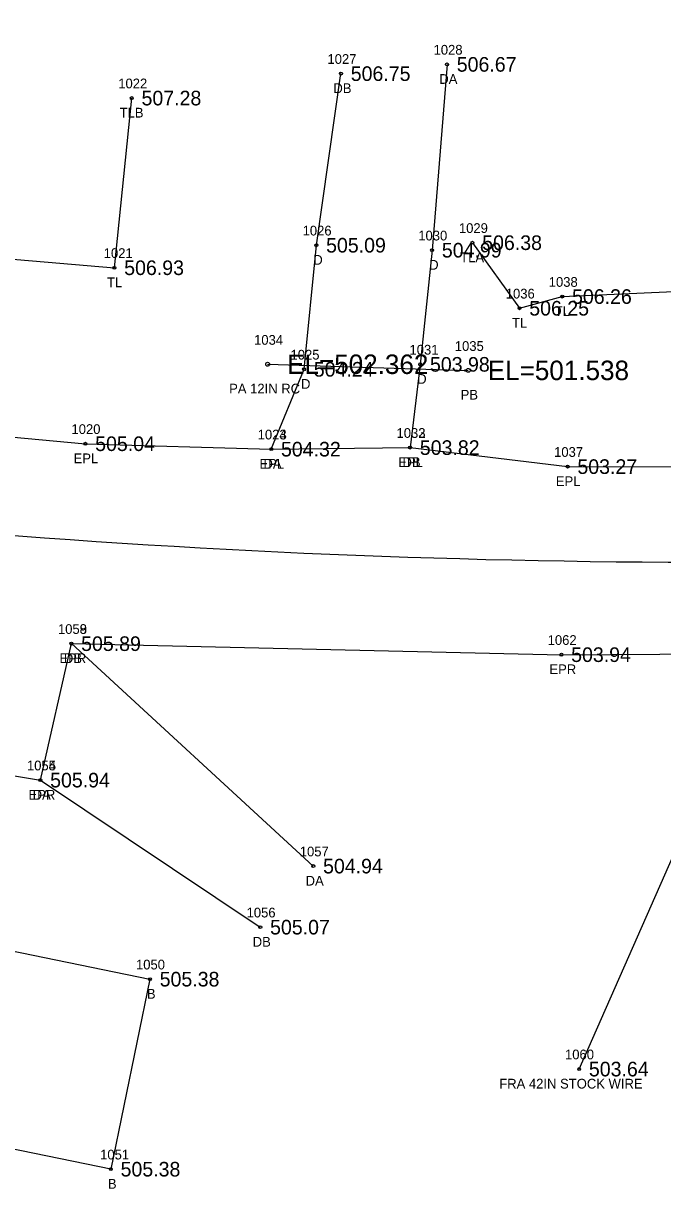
# Model space of a CAD drawing. Extents: x 1784103 to 1787401, y 770251 to 771298.
# Drawn here: x 1785175.5 to 1785241.1, y 770772 to 770891.7 of the extents above; entities that cross this region are included whole.
import ezdxf

# ---------------------------------------------------------------- set-up
doc = ezdxf.new("R2010")
doc.units = 0
for name, color, linetype in [('RD_EX_Bldg', 7, 'Continuous'), ('RD_EX_Bldg_txCode', 7, 'Continuous'), ('RD_EX_DR_Pipe', 7, 'Continuous'), ('RD_EX_DR_Pipe_txCode', 7, 'Continuous'), ('RD_EX_Driveway', 7, 'Continuous'), ('RD_EX_Driveway_txCode', 7, 'Continuous'), ('RD_EX_Fence_Other', 7, 'Continuous'), ('RD_EX_Fence_Other_txCode', 7, 'Continuous'), ('RD_EX_Road', 7, 'Continuous'), ('RD_EX_Road_txCode', 7, 'Continuous'), ('RD_EX_TX_Bldg_ELEV', 7, 'Continuous'), ('RD_EX_TX_Driveway_ELEV', 7, 'Continuous'), ('RD_EX_TX_Fence_Other_ELEV', 7, 'Continuous'), ('RD_EX_TX_Road_ELEV', 7, 'Continuous'), ('RD_EX_TX_VEG_ELEV', 7, 'Continuous'), ('RD_EX_VEG', 7, 'Continuous'), ('RD_EX_VEG_txCode', 7, 'Continuous'), ('RD_HC_Cl', 7, 'Continuous'), ('RD_SMD_Locator', 7, 'Continuous'), ('RD_TX_Pipe_ElevEX', 7, 'Continuous')]:
    doc.layers.add(name, color=color, linetype=linetype)

msp = doc.modelspace()

# ---------------------------------------------------------------- linework, layer by layer
at = {"layer": 'RD_EX_Bldg'}
msp.add_lwpolyline([(1785151.62, 770780.79), (1785156.03, 770800.21), (1785188.51, 770793.55), (1785184.5, 770774.04), (1785151.62, 770780.79)], dxfattribs=at)
at = {"layer": 'RD_EX_DR_Pipe'}
msp.add_line((1785200.59, 770856.69), (1785221.18, 770856.06), dxfattribs=at)
at = {"layer": 'RD_EX_Driveway'}
for p, q in [((1785205.28, 770805.16), (1785180.45, 770828)), ((1785177.27, 770813.99), (1785199.84, 770798.89))]:
    msp.add_line(p, q, dxfattribs=at)
for points in [[(1785219, 770887.48), (1785217.47, 770868.4), (1785216.25, 770856.68), (1785215.21, 770848.13)], [(1785200.96, 770847.97), (1785204.33, 770856.17), (1785205.59, 770868.91), (1785208.12, 770886.53)]]:
    msp.add_lwpolyline(points, dxfattribs=at)
at = {"layer": 'RD_EX_Fence_Other'}
msp.add_lwpolyline([(1785232.56, 770784.32), (1785243.65, 770809.45), (1785281.87, 770810.97), (1785330.77, 770810.35), (1785381.35, 770812.32), (1785481.48, 770815.35), (1785580.21, 770817.42), (1785680.43, 770820.14), (1785794.9, 770821.68), (1785847.9, 770822.69), (1785879.84, 770822.3), (1785979.43, 770826.69), (1786080.46, 770830.52), (1786182.98, 770833.3), (1786235.76, 770836.16), (1786247.48, 770836.31), (1786280.27, 770837.57), (1786379.57, 770841.87), (1786481.1, 770846.08), (1786539.49, 770848.17), (1786546.34, 770841.89)], dxfattribs=at)
at = {"layer": 'RD_EX_Road'}
for points in [[(1785083.87, 770860.72), (1785132.91, 770853.08), (1785181.89, 770848.53), (1785200.96, 770847.97), (1785215.21, 770848.13), (1785231.38, 770846.18), (1785281.19, 770846.16), (1785330.68, 770847.27), (1785380.41, 770849.82), (1785480.96, 770852.71), (1785580.09, 770856.45), (1785680.2, 770859.84), (1785779.71, 770863.4)], [(1785079.74, 770841.1), (1785077.36, 770829.81), (1785127.59, 770822.23), (1785177.27, 770813.99), (1785180.45, 770828), (1785230.74, 770826.87), (1785281.16, 770827.18), (1785331.14, 770828.42), (1785381.03, 770830.27), (1785481.34, 770833.99), (1785580.1, 770837.94), (1785680.6, 770840.57), (1785780.28, 770843.87)]]:
    msp.add_lwpolyline(points, dxfattribs=at)
at = {"layer": 'RD_EX_VEG'}
for points in [[(1785221.61, 770869.17), (1785226.44, 770862.44), (1785230.83, 770863.64), (1785281.61, 770865.88), (1785330.18, 770866.95), (1785378.64, 770865.28), (1785481.03, 770871.22), (1785579.9, 770882.43), (1785678.49, 770873.66), (1785753.25, 770880.69), (1785777.57, 770887.66), (1785796.72, 770894.6), (1785878.49, 770883.8), (1786077.63, 770894.05), (1786177.75, 770898.7), (1786232.19, 770912.93), (1786276.99, 770915.77), (1786313.89, 770919.94), (1786357.9, 770947.77)], [(1785087.02, 770879.15), (1785135.13, 770870.83), (1785184.87, 770866.6), (1785186.65, 770884.02)]]:
    msp.add_lwpolyline(points, dxfattribs=at)
at = {"layer": 'RD_HC_Cl'}
msp.add_arc((1785246.88, 771791.29), 954.93, 251.4323, 271.9359, dxfattribs=at)
at = {"layer": 'RD_SMD_Locator'}
for centre, radius in [((1785208.12, 770886.53), 0.15), ((1785219, 770887.48), 0.15), ((1785186.65, 770884.02), 0.15), ((1785205.59, 770868.91), 0.15), ((1785221.61, 770869.17), 0.15), ((1785217.47, 770868.4), 0.15), ((1785184.87, 770866.6), 0.15), ((1785230.83, 770863.64), 0.15), ((1785226.44, 770862.44), 0.15), ((1785200.59, 770856.69), 0.2), ((1785216.25, 770856.68), 0.15), ((1785204.33, 770856.17), 0.15), ((1785221.18, 770856.06), 0.2), ((1785181.89, 770848.53), 0.15), ((1785200.96, 770847.97), 0.15), ((1785200.96, 770847.97), 0.15), ((1785215.21, 770848.13), 0.15), ((1785215.21, 770848.13), 0.15), ((1785231.38, 770846.18), 0.15), ((1785180.45, 770828), 0.15), ((1785180.45, 770828), 0.15), ((1785230.74, 770826.87), 0.15), ((1785177.27, 770813.99), 0.15), ((1785177.27, 770813.99), 0.15), ((1785205.28, 770805.16), 0.15), ((1785199.84, 770798.89), 0.15), ((1785188.51, 770793.55), 0.15), ((1785232.56, 770784.32), 0.15), ((1785184.5, 770774.04), 0.15)]:
    msp.add_circle(centre, radius, dxfattribs=at)

# ---------------------------------------------------------------- texts
at = {"layer": 'RD_EX_Bldg_txCode'}
for s, p in [('1050', (1785187.08, 770794.55)), ('B', (1785188.2, 770791.55)), ('1051', (1785183.4, 770775.04)), ('B', (1785184.2, 770772.04))]:
    msp.add_text(s, height=1, dxfattribs=at).set_placement(p)
at = {"layer": 'RD_EX_DR_Pipe_txCode'}
for s, p in [('1034', (1785199.2, 770858.69)), ('1035', (1785219.8, 770858.06)), ('PA 12IN RC', (1785196.64, 770853.69)), ('PB', (1785220.4, 770853.06))]:
    msp.add_text(s, height=1, dxfattribs=at).set_placement(p)
at = {"layer": 'RD_EX_Driveway_txCode'}
for s, p in [('1028', (1785217.62, 770888.48)), ('1027', (1785206.73, 770887.53)), ('DB', (1785207.34, 770884.53)), ('DA', (1785218.21, 770885.48)), ('1026', (1785204.18, 770869.91)), ('1030', (1785216.05, 770869.4)), ('D', (1785205.28, 770866.91)), ('D', (1785217.17, 770866.4)), ('1025', (1785202.94, 770857.17)), ('1031', (1785215.15, 770857.68)), ('D', (1785215.94, 770854.68)), ('D', (1785204.02, 770854.17)), ('1024', (1785199.57, 770848.97)), ('1033', (1785213.82, 770849.13)), ('DA', (1785200.16, 770845.97)), ('DB', (1785214.43, 770846.13)), ('1058', (1785179.07, 770829)), ('DB', (1785179.68, 770826)), ('1055', (1785175.89, 770814.99)), ('DA', (1785176.48, 770811.99)), ('1057', (1785203.89, 770806.16)), ('DA', (1785204.49, 770803.16)), ('1056', (1785198.43, 770799.89)), ('DB', (1785199.06, 770796.89))]:
    msp.add_text(s, height=1, dxfattribs=at).set_placement(p)
at = {"layer": 'RD_EX_Fence_Other_txCode'}
for s, p in [('1060', (1785231.11, 770785.32)), ('FRA 42IN STOCK WIRE', (1785224.36, 770782.32))]:
    msp.add_text(s, height=1, dxfattribs=at).set_placement(p)
at = {"layer": 'RD_EX_Road_txCode'}
for s, p in [('1020', (1785180.46, 770849.53)), ('1023', (1785199.57, 770848.97)), ('1032', (1785213.82, 770849.13)), ('EPL', (1785180.68, 770846.53)), ('1037', (1785229.99, 770847.18)), ('EPL', (1785199.75, 770845.97)), ('EPL', (1785214, 770846.13)), ('EPL', (1785230.17, 770844.18)), ('1059', (1785179.07, 770829)), ('1062', (1785229.33, 770827.87)), ('EPR', (1785179.23, 770826)), ('EPR', (1785229.51, 770824.87)), ('1054', (1785175.89, 770814.99)), ('EPR', (1785176.05, 770811.99))]:
    msp.add_text(s, height=1, dxfattribs=at).set_placement(p)
at = {"layer": 'RD_EX_TX_Bldg_ELEV'}
for p in [(1785189.51, 770792.8), (1785185.5, 770773.29)]:
    msp.add_text('505.38', height=1.5, dxfattribs=at).set_placement(p)
at = {"layer": 'RD_EX_TX_Driveway_ELEV'}
for s, p in [('506.67', (1785220, 770886.73)), ('506.75', (1785209.12, 770885.78)), ('505.09', (1785206.59, 770868.16)), ('504.99', (1785218.47, 770867.65)), ('504.24', (1785205.33, 770855.42)), ('503.98', (1785217.25, 770855.93)), ('504.32', (1785201.96, 770847.22)), ('503.82', (1785216.21, 770847.38)), ('505.89', (1785181.45, 770827.25)), ('505.94', (1785178.27, 770813.24)), ('504.94', (1785206.28, 770804.41)), ('505.07', (1785200.84, 770798.14))]:
    msp.add_text(s, height=1.5, dxfattribs=at).set_placement(p)
at = {"layer": 'RD_EX_TX_Fence_Other_ELEV'}
msp.add_text('503.64', height=1.5, dxfattribs=at).set_placement((1785233.56, 770783.57))
at = {"layer": 'RD_EX_TX_Road_ELEV'}
for s, p in [('505.04', (1785182.89, 770847.78)), ('504.32', (1785201.96, 770847.22)), ('503.82', (1785216.21, 770847.38)), ('503.27', (1785232.38, 770845.43)), ('505.89', (1785181.45, 770827.25)), ('503.94', (1785231.74, 770826.12)), ('505.94', (1785178.27, 770813.24))]:
    msp.add_text(s, height=1.5, dxfattribs=at).set_placement(p)
at = {"layer": 'RD_EX_TX_VEG_ELEV'}
for s, p in [('507.28', (1785187.65, 770883.27)), ('506.38', (1785222.61, 770868.42)), ('506.93', (1785185.87, 770865.85)), ('506.26', (1785231.83, 770862.89)), ('506.25', (1785227.44, 770861.69))]:
    msp.add_text(s, height=1.5, dxfattribs=at).set_placement(p)
at = {"layer": 'RD_EX_VEG_txCode'}
for s, p in [('1022', (1785185.26, 770885.02)), ('TLB', (1785185.4, 770882.02)), ('1029', (1785220.22, 770870.17)), ('1021', (1785183.77, 770867.6)), ('TLA', (1785220.35, 770867.17)), ('TL', (1785184.1, 770864.6)), ('1038', (1785229.44, 770864.64)), ('1036', (1785225.03, 770863.44)), ('TL', (1785230.05, 770861.64)), ('TL', (1785225.67, 770860.44))]:
    msp.add_text(s, height=1, dxfattribs=at).set_placement(p)
at = {"layer": 'RD_TX_Pipe_ElevEX'}
for s, p in [('EL=502.362', (1785202.59, 770855.69)), ('EL=501.538', (1785223.18, 770855.06))]:
    msp.add_text(s, height=2, dxfattribs=at).set_placement(p)

doc.saveas('drawing.dxf')
